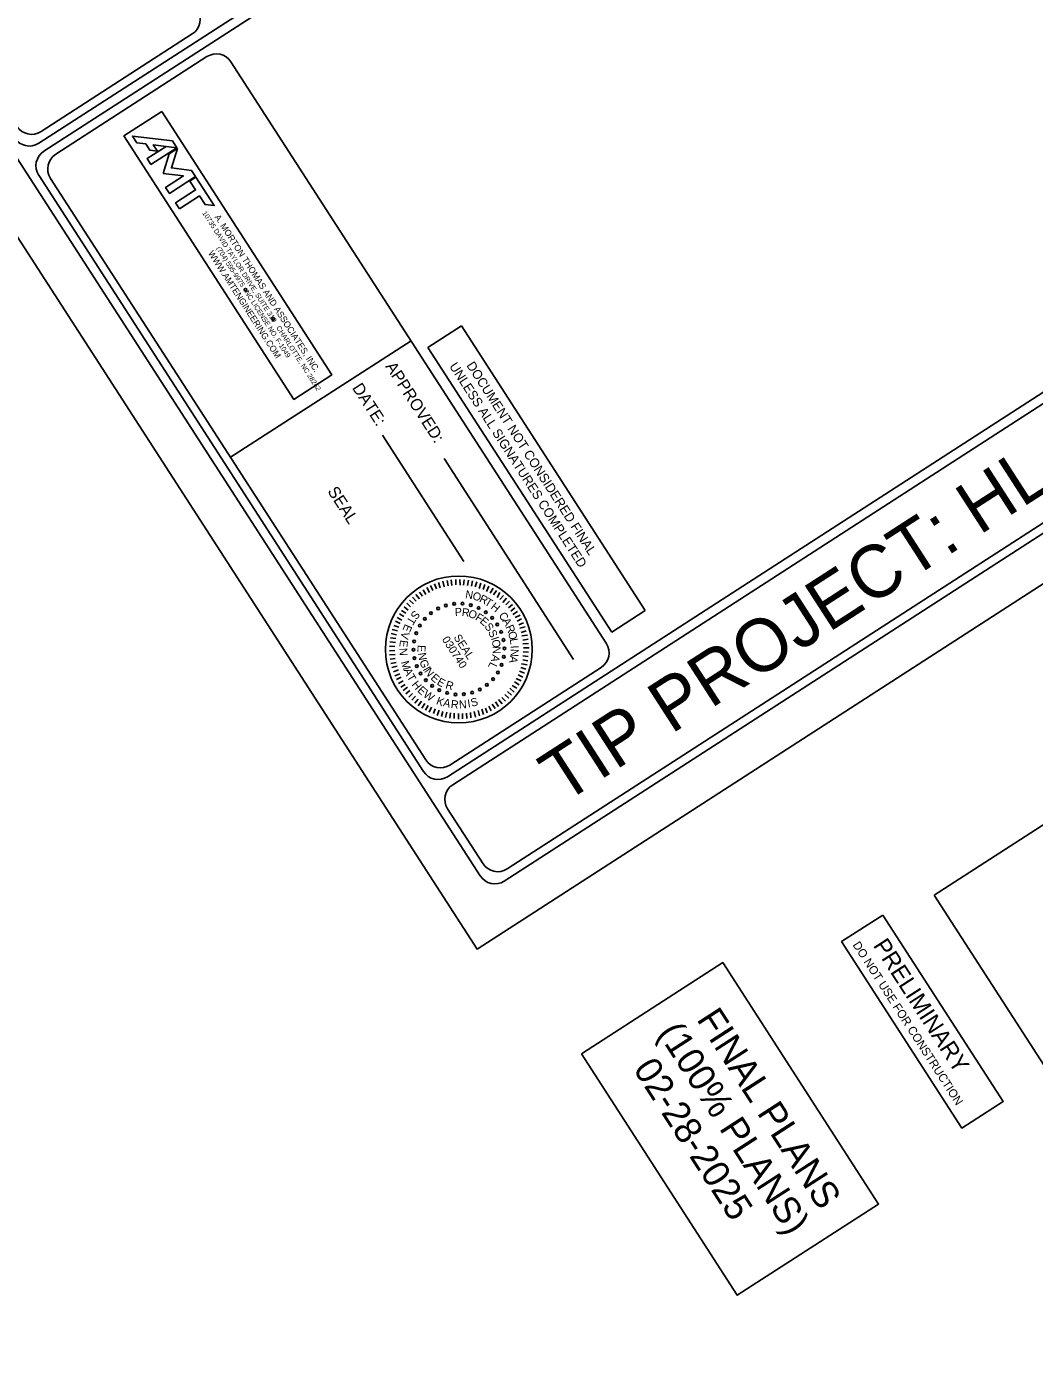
# Model space of a CAD drawing. Extents: x 2160312 to 2162215, y 789569 to 792090.
# Drawn here: x 2161025 to 2161620, y 789838 to 790620 of the extents above; entities that cross this region are included whole.
import ezdxf

# ---------------------------------------------------------------- set-up
doc = ezdxf.new("R2010")
doc.units = 0
for name, color, linetype in [('DEV PRELIMINARY STAMP CELL', 7, 'Continuous'), ('DEV TITLE SHEET CELL', 7, 'Continuous'), ('Gray Area Fill Shapes', 7, 'Continuous'), ('Old_Level_9', 7, 'Continuous'), ('Prop Grid Mask', 7, 'Continuous'), ('Sheet Block Title CELL', 7, 'Continuous'), ('Sheet Plot Border Outside CELL', 7, 'Continuous'), ('Sheet Sticker Exception Certification CELL', 7, 'Continuous'), ('Sheet Sticker Incomplete CELL', 7, 'Continuous')]:
    doc.layers.add(name, color=color, linetype=linetype)

msp = doc.modelspace()

# ---------------------------------------------------------------- linework, layer by layer
at = {"layer": 'DEV PRELIMINARY STAMP CELL'}
msp.add_lwpolyline([(2161530.5, 790095.42), (2161601.55, 789985.36), (2161577.26, 789969.68), (2161506.21, 790079.75)], close=True, dxfattribs=at)
msp.add_lwpolyline([(2161530.5, 790095.42), (2161601.55, 789985.36), (2161577.26, 789969.68), (2161506.21, 790079.75)], close=True, dxfattribs=at)
at = {"layer": 'DEV TITLE SHEET CELL'}
for p, q in [((2160490.55, 791361.48), (2161292.92, 790118.52)), ((2161888.56, 791103.58), (2161032.36, 790550.88)), ((2161891.61, 791098.86), (2161035.42, 790546.16)), ((2162129.87, 790729.77), (2161273.67, 790177.07)), ((2161276.72, 790172.34), (2162132.92, 790725.04)), ((2161307.13, 790115.46), (2162171.97, 790673.74)), ((2161385.31, 790172.04), (2162164.86, 790675.27)), ((2161122.96, 790615.37), (2161033.72, 790557.76)), ((2161131.6, 790601.99), (2161042.36, 790544.38)), ((2161367.33, 790255.78), (2161145.82, 790598.92)), ((2161259.45, 790180.13), (2161032.35, 790531.94)), ((2161260.81, 790187.01), (2161039.3, 790530.16)), ((2161252.08, 790434.32), (2161145.51, 790365.62)), ((2161235.24, 790378.64), (2161283.33, 790304.03)), ((2161271.56, 790364.88), (2161347.99, 790246.29)), ((2161364.27, 790241.56), (2161275.03, 790183.95)), ((2161385.31, 790172.04), (2161308.8, 790122.65)), ((2161294.58, 790125.72), (2161273.66, 790158.12))]:
    msp.add_line(p, q, dxfattribs=at)
msp.add_circle((2161280.29, 790252.14), 43.34, dxfattribs=at)
for centre, start, end in [((2161117.38, 790624.01), 302.84337, 32.84337), ((2161137.18, 790593.35), 32.84331, 122.84331), ((2161028.14, 790566.4), 212.84337, 302.84337), ((2161026.78, 790559.52), 212.84337, 302.84337), ((2161040.99, 790537.51), 122.84337, 212.84337), ((2161047.94, 790535.74), 122.84331, 212.84331), ((2161358.69, 790250.2), 302.84337, 32.84337), ((2161269.45, 790192.59), 212.84337, 302.84337), ((2161268.09, 790185.71), 212.84337, 302.84337), ((2161282.3, 790163.7), 122.84337, 212.84337), ((2161303.22, 790131.3), 212.84337, 302.84337), ((2161301.56, 790124.1), 212.84338, 302.84337)]:
    msp.add_arc(centre, 10.29, start, end, dxfattribs=at)
at = {"layer": 'Gray Area Fill Shapes'}
msp.add_lwpolyline([(2161530.5, 790095.42), (2161601.55, 789985.36), (2161577.26, 789969.68), (2161506.21, 790079.75)], close=True, dxfattribs=at)
at = {"layer": 'Old_Level_9'}
for p, q in [((2161278.45, 790293.43), (2161278.57, 790290.23)), ((2161257.05, 790286.01), (2161258.95, 790283.52)), ((2161259.25, 790287.43), (2161260.74, 790284.67)), ((2161261.32, 790288.62), (2161262.97, 790285.82)), ((2161263.66, 790289.83), (2161265.04, 790287)), ((2161265.86, 790290.8), (2161267.03, 790287.84)), ((2161268.4, 790291.7), (2161269.36, 790288.6)), ((2161270.8, 790292.36), (2161271.72, 790289.09)), ((2161273.34, 790292.81), (2161273.92, 790289.61)), ((2161275.77, 790293.19), (2161276.14, 790289.85)), ((2161280.87, 790293.36), (2161281, 790290.16)), ((2161283.54, 790293.14), (2161283.15, 790290.06)), ((2161285.96, 790293.07), (2161285.47, 790289.92)), ((2161288.38, 790292.55), (2161287.82, 790289.51)), ((2161290.91, 790292.1), (2161290, 790289.13)), ((2161293.36, 790291.3), (2161292.24, 790288.19)), ((2161295.7, 790290.43), (2161294.62, 790287.5)), ((2161297.94, 790289.5), (2161296.65, 790286.43)), ((2161300.49, 790288.32), (2161298.78, 790285.43)), ((2161302.55, 790286.97), (2161300.75, 790284.46)), ((2161304.54, 790285.72), (2161302.84, 790282.84)), ((2161249.56, 790279.39), (2161251.82, 790277.28)), ((2161251.15, 790281.31), (2161253.48, 790279.09)), ((2161253.05, 790282.98), (2161255.17, 790280.63)), ((2161255.02, 790284.55), (2161257.09, 790282.02)), ((2161306.6, 790283.93), (2161304.55, 790281.56)), ((2161308.52, 790282.34), (2161306.37, 790279.91)), ((2161310.22, 790280.61), (2161308.04, 790278.46)), ((2161311.96, 790278.61), (2161309.58, 790276.77)), ((2161243.86, 790270.95), (2161246.68, 790269.35)), ((2161245.24, 790273.18), (2161247.89, 790271.62)), ((2161246.49, 790275.18), (2161249.03, 790273.54)), ((2161248.04, 790277.37), (2161250.41, 790275.33)), ((2161313.36, 790276.68), (2161311.04, 790274.74)), ((2161314.99, 790274.61), (2161312.26, 790272.85)), ((2161316.41, 790272.41), (2161313.48, 790270.96)), ((2161317.39, 790270.21), (2161314.73, 790268.79)), ((2161240.98, 790263.88), (2161244.16, 790263.11)), ((2161241.85, 790266.23), (2161244.88, 790265.21)), ((2161242.86, 790268.81), (2161245.71, 790267.39)), ((2161318.5, 790267.8), (2161315.64, 790266.7)), ((2161319.36, 790265.53), (2161316.37, 790264.64)), ((2161320.02, 790263.13), (2161317.03, 790262.24)), ((2161239.59, 790256.59), (2161242.88, 790256.33)), ((2161240, 790258.94), (2161243.08, 790258.55)), ((2161240.39, 790261.57), (2161243.46, 790260.73)), ((2161320.82, 790260.52), (2161317.48, 790260.15)), ((2161321.13, 790258.19), (2161318.1, 790257.58)), ((2161321.51, 790255.76), (2161318.17, 790255.39)), ((2161239.31, 790254.03), (2161242.53, 790253.88)), ((2161239.37, 790251.39), (2161242.56, 790251.52)), ((2161239.48, 790248.93), (2161242.7, 790249.23)), ((2161239.75, 790246.43), (2161242.81, 790246.76)), ((2161321.29, 790248.03), (2161318.1, 790248.35)), ((2161321.46, 790250.52), (2161318.35, 790250.74)), ((2161321.75, 790253.09), (2161318.42, 790253.17)), ((2161240.2, 790243.89), (2161243.4, 790244.47)), ((2161240.75, 790241.42), (2161243.81, 790242.21)), ((2161241.75, 790238.94), (2161244.61, 790240.04)), ((2161319.06, 790238.11), (2161316.17, 790239.37)), ((2161319.86, 790240.56), (2161316.89, 790241.47)), ((2161320.59, 790243.12), (2161317.38, 790243.72)), ((2161321.01, 790245.47), (2161318.03, 790245.93)), ((2161242.52, 790236.61), (2161245.48, 790237.78)), ((2161243.49, 790234.41), (2161246.21, 790235.72)), ((2161244.7, 790232.07), (2161247.5, 790233.73)), ((2161246.02, 790229.8), (2161248.65, 790231.49)), ((2161315.88, 790231.29), (2161313.09, 790233.07)), ((2161317.09, 790233.56), (2161314.23, 790234.99)), ((2161318.13, 790235.87), (2161315.23, 790237.13)), ((2161247.42, 790227.87), (2161250.01, 790229.84)), ((2161248.98, 790225.9), (2161251.3, 790227.85)), ((2161250.72, 790223.9), (2161253.01, 790226.12)), ((2161252.53, 790222.24), (2161254.65, 790224.5)), ((2161307.93, 790221.7), (2161305.78, 790223.88)), ((2161309.72, 790223.31), (2161307.5, 790225.59)), ((2161311.38, 790225.12), (2161308.95, 790227.27)), ((2161312.97, 790227.04), (2161310.37, 790229.23)), ((2161314.63, 790229.3), (2161311.88, 790230.8)), ((2161254.24, 790220.52), (2161256.36, 790222.78)), ((2161256.33, 790218.89), (2161258.28, 790221.64)), ((2161258.46, 790217.44), (2161260.24, 790220.22)), ((2161260.56, 790216.27), (2161262.23, 790218.98)), ((2161262.83, 790215.05), (2161264.12, 790218.12)), ((2161265.28, 790214.26), (2161266.36, 790217.19)), ((2161267.59, 790213.22), (2161268.64, 790216.42)), ((2161270.07, 790212.59), (2161270.88, 790215.49)), ((2161290.08, 790212.26), (2161289.26, 790215.6)), ((2161292.58, 790212.98), (2161291.62, 790216.08)), ((2161294.92, 790213.75), (2161293.96, 790216.85)), ((2161297.12, 790214.72), (2161296.01, 790217.58)), ((2161299.46, 790215.93), (2161298.04, 790218.59)), ((2161301.73, 790217.25), (2161300.04, 790219.88)), ((2161303.73, 790218.54), (2161302.03, 790221.17)), ((2161305.86, 790220.07), (2161303.79, 790222.6)), ((2161272.39, 790212), (2161273.16, 790215.18)), ((2161275.02, 790211.61), (2161275.41, 790214.69)), ((2161277.58, 790211.33), (2161277.63, 790214.49)), ((2161280.14, 790211.05), (2161280.05, 790214.42)), ((2161282.43, 790211.19), (2161282.41, 790214.45)), ((2161285.11, 790211.43), (2161284.77, 790214.49)), ((2161287.43, 790211.74), (2161287.2, 790214.87))]:
    msp.add_line(p, q, dxfattribs=at)
for centre in [(2161272.64, 790278.12), (2161277.5, 790279.11), (2161282.46, 790279.18), (2161287.34, 790278.34), (2161260.26, 790270.2), (2161263.87, 790273.59), (2161268.05, 790276.26), (2161291.99, 790276.62), (2161296.24, 790274.08), (2161299.96, 790270.79), (2161255.19, 790261.73), (2161257.33, 790266.2), (2161303, 790266.88), (2161305.28, 790262.48), (2161253.91, 790256.94), (2161306.71, 790257.73), (2161253.52, 790252), (2161254.05, 790247.07), (2161306.85, 790247.86), (2161307.24, 790252.8), (2161255.48, 790242.33), (2161257.76, 790237.92), (2161303.42, 790238.6), (2161305.57, 790243.07), (2161260.8, 790234.01), (2161264.51, 790230.73), (2161296.88, 790231.21), (2161300.5, 790234.6), (2161268.77, 790228.18), (2161273.41, 790226.46), (2161278.3, 790225.62), (2161283.26, 790225.7), (2161288.11, 790226.68), (2161292.71, 790228.54)]:
    msp.add_circle(centre, 0.788, dxfattribs=at)
at = {"layer": 'Prop Grid Mask'}
msp.add_lwpolyline([(2161104.97, 790569.64), (2161205.32, 790414.19), (2161182.95, 790399.75), (2161082.6, 790555.2)], close=True, dxfattribs=at)
at = {"layer": 'Sheet Block Title CELL'}
msp.add_lwpolyline([(2161104.97, 790569.64), (2161205.32, 790414.19), (2161182.95, 790399.75), (2161082.6, 790555.2)], close=True, dxfattribs=at)
for points in [[(2161107.5, 790549.03), (2161113.91, 790548.17), (2161111.25, 790552.29), (2161087.64, 790555.13), (2161090.22, 790551.14), (2161095.52, 790550.51), (2161097.88, 790546.86), (2161102.41, 790546.22), (2161099.97, 790550), (2161107.5, 790549.03)], [(2161098.54, 790538.25), (2161113.91, 790548.17), (2161107.5, 790549.03), (2161096.26, 790541.78), (2161098.54, 790538.25)], [(2161105.71, 790533.09), (2161117.71, 790531.59), (2161107.22, 790524.81), (2161109.49, 790521.29), (2161124.86, 790531.21), (2161122.59, 790534.74), (2161110.7, 790536.31), (2161114.2, 790547.72), (2161109.31, 790544.56), (2161105.71, 790533.09)], [(2161115.38, 790512.17), (2161127.23, 790519.81), (2161130.52, 790514.71), (2161135.95, 790514.04), (2161125.15, 790530.76), (2161121.63, 790528.48), (2161124.95, 790523.34), (2161113.1, 790515.69), (2161115.38, 790512.17)]]:
    msp.add_lwpolyline(points, dxfattribs=at)
for centre in [(2161154.42, 790464.37), (2161170.69, 790447.19)]:
    msp.add_circle(centre, 0.833, dxfattribs=at)
at = {"layer": 'Sheet Plot Border Outside CELL'}
msp.add_lwpolyline([(2160375.57, 791493.51), (2161291.05, 790075.32), (2162215.22, 790671.9), (2161299.74, 792090.09)], close=True, dxfattribs=at)
at = {"layer": 'Sheet Sticker Exception Certification CELL'}
for p, q in [((2161262.1, 790430.39), (2161281.84, 790443.13)), ((2161281.84, 790443.13), (2161390.33, 790275.07)), ((2161370.59, 790262.33), (2161262.1, 790430.39)), ((2161390.32, 790275.06), (2161370.58, 790262.32))]:
    msp.add_line(p, q, dxfattribs=at)
at = {"layer": 'Sheet Sticker Incomplete CELL'}
for points in [[(2161560.88, 790107.2), (2161656.63, 790169.01), (2161830.49, 789899.67), (2161734.74, 789837.86)], [(2161352.65, 790013.54), (2161436.03, 790067.36), (2161528.03, 789924.84), (2161444.66, 789871.02)]]:
    msp.add_lwpolyline(points, close=True, dxfattribs=at)

# ---------------------------------------------------------------- texts
at = {"layer": 'DEV PRELIMINARY STAMP CELL'}
for s, height, p in [('DO NOT USE FOR CONSTRUCTION', 5.0001, (2161512.56, 790077.81)), (' PRELIMINARY', 9.9999, (2161522.51, 790080.59))]:
    msp.add_text(s, height=height, rotation=302.84334, dxfattribs=at).set_placement(p)
at = {"layer": 'DEV TITLE SHEET CELL'}
for s, height, rotation, p in [('TIP PROJECT: HL-0025', 31, 32.84337, (2161341.74, 790160.67)), ('APPROVED:  ', 7, 302.80314, (2161236.71, 790419.2)), ('DATE:  ', 7, 302.80314, (2161217.07, 790406.52)), ('SEAL', 7, 302.80314, (2161202.52, 790345.58))]:
    msp.add_text(s, height=height, rotation=rotation, dxfattribs=at).set_placement(p)
at = {"layer": 'Old_Level_9'}
for s, height, rotation, p in [('N', 4.72, 350.90999, (2161283.87, 790282.49)), ('O', 4.72, 342.78755, (2161287.98, 790281.88)), ('R', 4.72, 335.01878, (2161292.02, 790280.47)), ('T', 4.72, 328.27912, (2161295.12, 790278.89)), ('H', 4.72, 320.58668, (2161298.69, 790276.59)), ('T', 4.72, 238.46772, (2161251.25, 790271.94)), ('S', 4.72, 231.05534, (2161254.14, 790275.58)), ('P', 4.7, 2.96698, (2161278.06, 790271.9)), ('R', 4.7, 352.59113, (2161281.87, 790271.98)), ('O', 4.7, 341.09515, (2161285.47, 790271.48)), ('F', 4.7, 329.24329, (2161289.64, 790269.86)), ('E', 4.7, 319.43227, (2161292.29, 790268.29)), ('C', 4.72, 307.78325, (2161303.58, 790272.01)), ('A', 4.72, 300.8182, (2161305.76, 790269.1)), ('E', 4.72, 246.66583, (2161248.65, 790267.48)), ('S', 4.7, 307.31136, (2161295.16, 790265.68)), ('S', 4.7, 295.88479, (2161297.44, 790262.39)), ('R', 4.72, 292.86489, (2161307.78, 790265.5)), ('O', 4.72, 285.93014, (2161309.22, 790262.11)), ('E', 4.72, 263.07458, (2161245.69, 790257.91)), ('V', 4.72, 254.77313, (2161246.85, 790262.95)), ('E', 4.7, 267.71253, (2161256.03, 790254.85)), ('030740', 4.699, 302.84334, (2161270.14, 790258.07)), ('SEAL', 4.699, 302.84334, (2161277.05, 790259.26)), ('I', 4.7, 288.3254, (2161299.19, 790258.76)), ('O', 4.7, 280.71822, (2161299.66, 790257.57)), ('L', 4.72, 278.58924, (2161310.31, 790258.35)), ('N', 4.72, 271.17233, (2161245.26, 790252.97)), ('N', 4.7, 278.9017, (2161256.24, 790249.93)), ('A', 4.7, 256.78711, (2161300.16, 790249.42)), ('N', 4.7, 270.23636, (2161300.33, 790253.99)), ('A', 4.72, 259.84841, (2161310.65, 790248.6)), ('N', 4.72, 267.74718, (2161310.95, 790252.52)), ('I', 4.72, 273.64929, (2161310.81, 790254.36)), ('M', 4.72, 285.18037, (2161246.11, 790244.73)), ('A', 4.72, 293.0255, (2161247.67, 790239.95)), ('G', 4.7, 290.32458, (2161256.93, 790245.17)), ('I', 4.7, 298.46792, (2161258.91, 790240.49)), ('N', 4.7, 305.97113, (2161259.72, 790239.23)), ('L', 4.7, 244.37564, (2161298.95, 790245.07)), ('T', 4.72, 300.22992, (2161249.39, 790235.99)), ('H', 4.72, 308.85455, (2161252.22, 790231.34)), ('E', 4.7, 318.64902, (2161263.3, 790234.85)), ('E', 4.7, 330.00015, (2161266.96, 790231.71)), ('R', 4.7, 343.1926, (2161272.06, 790229.34)), ('E', 4.72, 317.00809, (2161255.5, 790227.6)), ('W', 4.72, 324.8491, (2161258.86, 790224.62)), ('K', 4.72, 338.98434, (2161266.55, 790219.99)), ('S', 4.72, 15.10122, (2161288.01, 790218.25)), ('A', 4.72, 346.36503, (2161270.72, 790218.76)), ('R', 4.72, 353.99365, (2161275.39, 790217.67)), ('N', 4.72, 2.2159, (2161280.46, 790217.29)), ('I', 4.72, 8.88973, (2161285.76, 790217.84))]:
    msp.add_text(s, height=height, rotation=rotation, dxfattribs=at).set_placement(p)
at = {"layer": 'Sheet Block Title CELL'}
for s, height, p in [('10735 DAVID TAYLOR DRIVE, SUITE 310   CHARLOTTE, NC 28262', 2.9167, (2161128.71, 790509.67)), ('A. MORTON THOMAS AND ASSOCIATES, INC.', 3.75, (2161135.94, 790507.3)), ('(704) 595-9975   NC LICENSE NO. F-1049', 2.9167, (2161136.95, 790488.83)), ('WWW.AMTENGINEERING.COM', 3.75, (2161132.11, 790485.96))]:
    msp.add_text(s, height=height, rotation=302.84285, dxfattribs=at).set_placement(p)
at = {"layer": 'Sheet Sticker Exception Certification CELL'}
for s, p in [('UNLESS ALL SIGNATURES COMPLETED', (2161274.44, 790419.31)), ('DOCUMENT NOT CONSIDERED FINAL', (2161284.58, 790419.82))]:
    msp.add_text(s, height=5.5, rotation=302.84334, dxfattribs=at).set_placement(p)
at = {"layer": 'Sheet Sticker Incomplete CELL'}
for s, height, p in [('FINAL PLANS', 15.7916, (2161420.28, 790033.92)), ('(100% PLANS)', 15.7916, (2161397.33, 790025.79)), ('02-28-2025', 15.792, (2161382.86, 790004.53))]:
    msp.add_text(s, height=height, rotation=302.84334, dxfattribs=at).set_placement(p)

doc.saveas('drawing.dxf')
